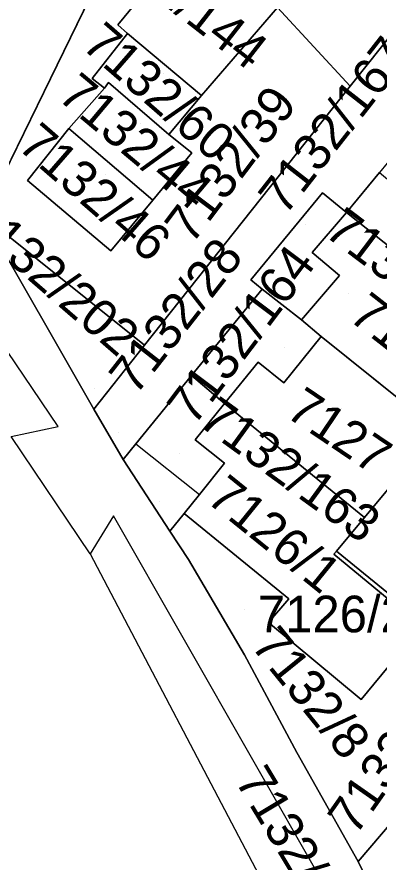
# Model space of a CAD drawing. Extents: x -266199 to -261993, y -1239047 to -1235108.
# Drawn here: x -263520.41 to -263500.66, y -1236178.02 to -1236131.86 of the extents above; entities that cross this region are included whole.
import ezdxf

# ---------------------------------------------------------------- set-up
doc = ezdxf.new("R2010")
doc.units = 0
for name, color, linetype in [('body_kn', 7, 'Continuous'), ('kladpar_druhypozemkov', 7, 'Continuous'), ('kladpar_hranice', 7, 'Continuous'), ('kladpar_parcelnecisla', 7, 'Continuous'), ('kladpar_plochy', 7, 'Continuous'), ('kladpar_sipky', 7, 'Continuous'), ('zappar_hrandruhpozemk', 7, 'Continuous')]:
    doc.layers.add(name, color=color, linetype=linetype)

msp = doc.modelspace()

# ---------------------------------------------------------------- linework, layer by layer
at = {"layer": 'body_kn'}
for p, q in [((-263514.91, -1236132.3), (-263514.91, -1236132.3)), ((-263514.38, -1236132.76), (-263514.38, -1236132.76)), ((-263516.31, -1236135.22), (-263516.31, -1236135.22)), ((-263515.41, -1236135.45), (-263515.41, -1236135.45)), ((-263515.64, -1236135.75), (-263515.64, -1236135.75)), ((-263502.23, -1236135.64), (-263502.23, -1236135.64)), ((-263510.35, -1236136.15), (-263510.35, -1236136.15)), ((-263510.35, -1236136.15), (-263510.35, -1236136.15)), ((-263517.58, -1236137.96), (-263517.58, -1236137.96)), ((-263517.58, -1236137.96), (-263517.58, -1236137.96)), ((-263512.12, -1236138.29), (-263512.12, -1236138.29)), ((-263510.87, -1236139.29), (-263510.87, -1236139.29)), ((-263519.84, -1236140.79), (-263519.84, -1236140.79)), ((-263503.75, -1236141.46), (-263503.75, -1236141.46)), ((-263503.75, -1236141.46), (-263503.75, -1236141.46)), ((-263512.99, -1236141.86), (-263512.99, -1236141.86)), ((-263512.99, -1236141.86), (-263512.99, -1236141.86)), ((-263502.44, -1236142.54), (-263502.44, -1236142.54)), ((-263502.44, -1236142.54), (-263502.44, -1236142.54)), ((-263515.29, -1236144.63), (-263515.29, -1236144.63)), ((-263504.3, -1236144.72), (-263504.3, -1236144.72)), ((-263502.81, -1236145.98), (-263502.81, -1236145.98)), ((-263507.65, -1236146.22), (-263507.65, -1236146.22)), ((-263507.03, -1236146.72), (-263507.03, -1236146.72)), ((-263504.88, -1236148.4), (-263504.88, -1236148.4)), ((-263504.88, -1236148.4), (-263504.88, -1236148.4)), ((-263503.81, -1236149.31), (-263503.81, -1236149.31)), ((-263503.81, -1236149.31), (-263503.81, -1236149.31)), ((-263513.45, -1236149.79), (-263513.45, -1236149.79)), ((-263507.26, -1236150.72), (-263507.26, -1236150.72)), ((-263510.89, -1236151.45), (-263510.89, -1236151.45)), ((-263510.89, -1236151.45), (-263510.89, -1236151.45)), ((-263505.86, -1236151.85), (-263505.86, -1236151.85)), ((-263509.09, -1236152.98), (-263509.09, -1236152.98)), ((-263516.21, -1236153.28), (-263516.21, -1236153.28)), ((-263516.21, -1236153.28), (-263516.21, -1236153.28)), ((-263518.16, -1236154.23), (-263518.16, -1236154.23)), ((-263518.16, -1236154.23), (-263518.16, -1236154.23)), ((-263510.69, -1236154.96), (-263510.69, -1236154.96)), ((-263513.93, -1236155.17), (-263513.93, -1236155.17)), ((-263513.93, -1236155.17), (-263513.93, -1236155.17)), ((-263514.62, -1236156.03), (-263514.62, -1236156.03)), ((-263514.62, -1236156.03), (-263514.62, -1236156.03)), ((-263509.09, -1236156.24), (-263509.09, -1236156.24)), ((-263510.45, -1236157.94), (-263510.45, -1236157.94)), ((-263510.45, -1236157.94), (-263510.45, -1236157.94)), ((-263515.14, -1236159.11), (-263515.14, -1236159.11)), ((-263511.29, -1236158.99), (-263511.29, -1236158.99)), ((-263511.29, -1236158.99), (-263511.29, -1236158.99)), ((-263501.45, -1236159.2), (-263501.45, -1236159.2)), ((-263512.07, -1236159.94), (-263512.07, -1236159.94)), ((-263512.07, -1236159.94), (-263512.07, -1236159.94)), ((-263516.41, -1236161.19), (-263516.41, -1236161.19)), ((-263516.41, -1236161.19), (-263516.41, -1236161.19)), ((-263503.12, -1236161.2), (-263503.12, -1236161.2)), ((-263503.12, -1236161.2), (-263503.12, -1236161.2)), ((-263502.98, -1236161.03), (-263502.98, -1236161.03)), ((-263511.06, -1236161.5), (-263511.06, -1236161.5)), ((-263505.57, -1236163.64), (-263505.57, -1236163.64)), ((-263506.69, -1236164.94), (-263506.69, -1236164.94)), ((-263508, -1236166.7), (-263508, -1236166.7)), ((-263501.64, -1236169.14), (-263501.64, -1236169.14)), ((-263505.14, -1236172.03), (-263505.14, -1236172.03)), ((-263501.79, -1236177.99), (-263501.79, -1236177.99))]:
    msp.add_line(p, q, dxfattribs=at)
at = {"layer": 'kladpar_druhypozemkov'}
for p, q in [((-263512.4, -1236134.97), (-263512.4, -1236134.97)), ((-263513.66, -1236137.67), (-263513.66, -1236137.67)), ((-263508.89, -1236138.85), (-263508.89, -1236138.85)), ((-263515.56, -1236140.44), (-263515.56, -1236140.44)), ((-263505.12, -1236145.98), (-263505.12, -1236145.98)), ((-263502.34, -1236146.95), (-263502.34, -1236146.95)), ((-263505.81, -1236149.91), (-263505.81, -1236149.91)), ((-263516.18, -1236152.13), (-263516.18, -1236152.13)), ((-263502.69, -1236153.25), (-263502.69, -1236153.25)), ((-263514.87, -1236154.53), (-263514.87, -1236154.53)), ((-263511.54, -1236155.68), (-263511.54, -1236155.68)), ((-263512.65, -1236158.34), (-263512.65, -1236158.34)), ((-263506.54, -1236158.92), (-263506.54, -1236158.92)), ((-263501.14, -1236162.66), (-263501.14, -1236162.66)), ((-263508, -1236164.25), (-263508, -1236164.25))]:
    msp.add_line(p, q, dxfattribs=at)
at = {"layer": 'kladpar_hranice'}
for p, q in [((-263503.75, -1236141.46), (-263502.44, -1236142.54)), ((-263502.44, -1236142.54), (-263495.11, -1236148.39)), ((-263503.81, -1236149.31), (-263499.04, -1236153.16)), ((-263509.09, -1236152.98), (-263510.89, -1236151.45))]:
    msp.add_line(p, q, dxfattribs=at)
for points in [[(-263510.25, -1236056.55), (-263509.34, -1236068.08), (-263508.78, -1236075.87), (-263508.53, -1236085.13), (-263507.31, -1236093.65), (-263507, -1236098.16), (-263506.93, -1236101.17), (-263507.02, -1236104.6), (-263507.26, -1236107.27), (-263507.94, -1236111.18), (-263508.5, -1236113.5), (-263509.38, -1236115.94), (-263510.54, -1236118.73), (-263522.26, -1236142.75)], [(-263501.54, -1236127.4), (-263502.26, -1236126.79), (-263507.09, -1236122.77), (-263510.96, -1236127.49), (-263514.91, -1236132.3), (-263514.38, -1236132.76), (-263516.31, -1236135.22), (-263515.64, -1236135.75), (-263517.58, -1236137.96), (-263519.84, -1236140.79), (-263515.29, -1236144.63), (-263512.99, -1236141.86), (-263510.87, -1236139.29), (-263512.12, -1236138.29), (-263510.35, -1236136.15), (-263506.2, -1236131.35), (-263502.23, -1236135.64), (-263513.45, -1236149.79), (-263522.26, -1236142.75), (-263510.54, -1236118.73), (-263500.84, -1236126.75), (-263501.54, -1236127.4)], [(-263498.03, -1236130.34), (-263502.23, -1236135.64), (-263506.2, -1236131.35), (-263502.26, -1236126.79), (-263501.54, -1236127.4), (-263498.03, -1236130.34)], [(-263506.2, -1236131.35), (-263510.35, -1236136.15), (-263514.38, -1236132.76), (-263514.91, -1236132.3), (-263510.96, -1236127.49), (-263506.2, -1236131.35)], [(-263514.62, -1236156.03), (-263516.21, -1236153.28), (-263513.45, -1236149.79), (-263502.23, -1236135.64), (-263498.03, -1236130.34), (-263497.41, -1236130.84), (-263499.87, -1236133.83), (-263497.35, -1236135.81), (-263498.77, -1236137.62), (-263498.54, -1236137.8), (-263500.64, -1236140.36), (-263502.44, -1236142.54), (-263503.75, -1236141.46), (-263507.65, -1236146.22), (-263507.03, -1236146.72), (-263510.89, -1236151.45), (-263513.93, -1236155.17), (-263514.62, -1236156.03)], [(-263510.35, -1236136.15), (-263512.12, -1236138.29), (-263515.41, -1236135.45), (-263515.64, -1236135.75), (-263516.31, -1236135.22), (-263514.38, -1236132.76), (-263510.35, -1236136.15)], [(-263517.58, -1236137.96), (-263515.64, -1236135.75), (-263515.41, -1236135.45), (-263512.12, -1236138.29), (-263510.87, -1236139.29), (-263512.99, -1236141.86), (-263517.58, -1236137.96)], [(-263512.99, -1236141.86), (-263515.29, -1236144.63), (-263519.84, -1236140.79), (-263517.58, -1236137.96), (-263512.99, -1236141.86)], [(-263492.76, -1236142.55), (-263491.31, -1236143.78), (-263495.11, -1236148.39), (-263502.44, -1236142.54), (-263500.64, -1236140.36)], [(-263504.88, -1236148.4), (-263507.03, -1236146.72), (-263507.65, -1236146.22), (-263503.75, -1236141.46)], [(-263522.26, -1236142.75), (-263516.21, -1236153.28), (-263514.62, -1236156.03), (-263512.07, -1236159.94), (-263511.06, -1236161.5), (-263508, -1236166.7), (-263505.14, -1236172.03), (-263501.79, -1236177.99), (-263500.21, -1236181.24), (-263498.9, -1236183.95), (-263497.65, -1236186.5), (-263496.56, -1236188.8), (-263492.22, -1236198.63), (-263490.17, -1236203.83), (-263488.26, -1236209.1), (-263484.59, -1236221.51), (-263481.5, -1236234.32), (-263480.57, -1236239.51), (-263477.77, -1236255.09), (-263476.89, -1236265.26)], [(-263516.21, -1236153.28), (-263522.26, -1236142.75), (-263513.45, -1236149.79), (-263516.21, -1236153.28)], [(-263504.88, -1236148.4), (-263502.81, -1236145.98), (-263504.3, -1236144.72), (-263502.44, -1236142.54)], [(-263502.44, -1236142.54), (-263504.3, -1236144.72), (-263502.81, -1236145.98), (-263504.88, -1236148.4)], [(-263510.89, -1236151.45), (-263507.03, -1236146.72), (-263504.88, -1236148.4), (-263503.81, -1236149.31)], [(-263495.11, -1236148.39), (-263499.04, -1236153.16), (-263503.81, -1236149.31), (-263504.88, -1236148.4)], [(-263509.09, -1236152.98), (-263507.26, -1236150.72), (-263505.86, -1236151.85), (-263503.81, -1236149.31)], [(-263503.81, -1236149.31), (-263505.86, -1236151.85), (-263507.26, -1236150.72), (-263509.09, -1236152.98)], [(-263512.07, -1236159.94), (-263514.62, -1236156.03), (-263513.93, -1236155.17), (-263510.89, -1236151.45), (-263509.09, -1236152.98)], [(-263510.45, -1236157.94), (-263509.09, -1236156.24), (-263510.69, -1236154.96), (-263509.09, -1236152.98)], [(-263509.09, -1236152.98), (-263510.69, -1236154.96), (-263509.09, -1236156.24), (-263510.45, -1236157.94)], [(-263509.09, -1236152.98), (-263501.45, -1236159.2), (-263502.98, -1236161.03), (-263503.12, -1236161.2)], [(-263499.04, -1236153.16), (-263497.49, -1236154.43), (-263501.45, -1236159.2), (-263509.09, -1236152.98)], [(-263494.63, -1236168.22), (-263498.34, -1236165.15), (-263498.18, -1236164.95), (-263502.98, -1236161.03), (-263501.45, -1236159.2), (-263497.49, -1236154.43), (-263489.56, -1236160.78), (-263489.65, -1236160.93), (-263493.09, -1236165.89), (-263494.47, -1236167.98), (-263494.63, -1236168.22)], [(-263510.45, -1236157.94), (-263511.29, -1236158.99), (-263512.07, -1236159.94)], [(-263503.12, -1236161.2), (-263498.34, -1236165.15), (-263501.64, -1236169.14), (-263506.69, -1236164.94), (-263505.57, -1236163.64), (-263511.29, -1236158.99), (-263510.45, -1236157.94)], [(-263511.29, -1236158.99), (-263505.57, -1236163.64), (-263506.69, -1236164.94), (-263501.64, -1236169.14), (-263498.34, -1236165.15), (-263494.63, -1236168.22), (-263496.43, -1236170.92), (-263499.88, -1236175.74), (-263501.79, -1236177.99), (-263505.14, -1236172.03), (-263508, -1236166.7), (-263511.06, -1236161.5), (-263512.07, -1236159.94), (-263511.29, -1236158.99)], [(-263498.34, -1236165.15), (-263503.12, -1236161.2), (-263502.98, -1236161.03), (-263498.18, -1236164.95), (-263498.34, -1236165.15)], [(-263500.21, -1236181.24), (-263501.79, -1236177.99), (-263499.88, -1236175.74), (-263497.84, -1236177.68), (-263500.21, -1236181.24)]]:
    msp.add_lwpolyline(points, dxfattribs=at)
at = {"layer": 'kladpar_plochy'}
msp.add_line((-263510.54, -1236118.73), (-263522.26, -1236142.75), dxfattribs=at)
for points in [[(-263501.54, -1236127.4), (-263502.26, -1236126.79), (-263507.09, -1236122.77), (-263510.96, -1236127.49), (-263514.91, -1236132.3), (-263514.38, -1236132.76), (-263516.31, -1236135.22), (-263515.64, -1236135.75), (-263517.58, -1236137.96), (-263519.84, -1236140.79), (-263515.29, -1236144.63), (-263512.99, -1236141.86), (-263510.87, -1236139.29), (-263512.12, -1236138.29), (-263510.35, -1236136.15), (-263506.2, -1236131.35), (-263502.23, -1236135.64), (-263513.45, -1236149.79), (-263522.26, -1236142.75), (-263510.54, -1236118.73), (-263500.84, -1236126.75)], [(-263498.03, -1236130.34), (-263502.23, -1236135.64), (-263506.2, -1236131.35), (-263502.26, -1236126.79), (-263501.54, -1236127.4)], [(-263506.2, -1236131.35), (-263510.35, -1236136.15), (-263514.38, -1236132.76), (-263514.91, -1236132.3), (-263510.96, -1236127.49)], [(-263514.62, -1236156.03), (-263516.21, -1236153.28), (-263513.45, -1236149.79), (-263502.23, -1236135.64), (-263498.03, -1236130.34), (-263497.41, -1236130.84), (-263499.87, -1236133.83), (-263497.35, -1236135.81), (-263498.77, -1236137.62), (-263498.54, -1236137.8), (-263500.64, -1236140.36), (-263502.44, -1236142.54), (-263503.75, -1236141.46), (-263507.65, -1236146.22), (-263507.03, -1236146.72), (-263510.89, -1236151.45), (-263513.93, -1236155.17)], [(-263510.35, -1236136.15), (-263512.12, -1236138.29), (-263515.41, -1236135.45), (-263515.64, -1236135.75), (-263516.31, -1236135.22), (-263514.38, -1236132.76)], [(-263517.58, -1236137.96), (-263515.64, -1236135.75), (-263515.41, -1236135.45), (-263512.12, -1236138.29), (-263510.87, -1236139.29), (-263512.99, -1236141.86)], [(-263512.99, -1236141.86), (-263515.29, -1236144.63), (-263519.84, -1236140.79), (-263517.58, -1236137.96)], [(-263492.76, -1236142.55), (-263491.31, -1236143.78), (-263495.11, -1236148.39), (-263502.44, -1236142.54), (-263500.64, -1236140.36), (-263499.1, -1236141.63), (-263497.07, -1236139.01)], [(-263503.75, -1236141.46), (-263502.44, -1236142.54), (-263504.3, -1236144.72), (-263502.81, -1236145.98), (-263504.88, -1236148.4), (-263507.03, -1236146.72), (-263507.65, -1236146.22)], [(-263516.21, -1236153.28), (-263522.26, -1236142.75), (-263513.45, -1236149.79)], [(-263495.11, -1236148.39), (-263499.04, -1236153.16), (-263503.81, -1236149.31), (-263504.88, -1236148.4), (-263502.81, -1236145.98), (-263504.3, -1236144.72), (-263502.44, -1236142.54)], [(-263510.89, -1236151.45), (-263507.03, -1236146.72), (-263504.88, -1236148.4), (-263503.81, -1236149.31), (-263505.86, -1236151.85), (-263507.26, -1236150.72), (-263509.09, -1236152.98)], [(-263499.04, -1236153.16), (-263497.49, -1236154.43), (-263501.45, -1236159.2), (-263509.09, -1236152.98), (-263507.26, -1236150.72), (-263505.86, -1236151.85), (-263503.81, -1236149.31)], [(-263512.07, -1236159.94), (-263514.62, -1236156.03), (-263513.93, -1236155.17), (-263510.89, -1236151.45), (-263509.09, -1236152.98), (-263510.69, -1236154.96), (-263509.09, -1236156.24), (-263510.45, -1236157.94), (-263511.29, -1236158.99)], [(-263503.12, -1236161.2), (-263498.34, -1236165.15), (-263501.64, -1236169.14), (-263506.69, -1236164.94), (-263505.57, -1236163.64), (-263511.29, -1236158.99), (-263510.45, -1236157.94), (-263509.09, -1236156.24), (-263510.69, -1236154.96), (-263509.09, -1236152.98), (-263501.45, -1236159.2), (-263502.98, -1236161.03)], [(-263494.63, -1236168.22), (-263498.34, -1236165.15), (-263498.18, -1236164.95), (-263502.98, -1236161.03), (-263501.45, -1236159.2), (-263497.49, -1236154.43), (-263489.56, -1236160.78), (-263489.65, -1236160.93), (-263493.09, -1236165.89), (-263494.47, -1236167.98)], [(-263511.29, -1236158.99), (-263505.57, -1236163.64), (-263506.69, -1236164.94), (-263501.64, -1236169.14), (-263498.34, -1236165.15), (-263494.63, -1236168.22), (-263496.43, -1236170.92), (-263499.88, -1236175.74), (-263501.79, -1236177.99), (-263505.14, -1236172.03), (-263508, -1236166.7), (-263511.06, -1236161.5), (-263512.07, -1236159.94)], [(-263498.34, -1236165.15), (-263503.12, -1236161.2), (-263502.98, -1236161.03), (-263498.18, -1236164.95)], [(-263500.21, -1236181.24), (-263501.79, -1236177.99), (-263499.88, -1236175.74), (-263497.84, -1236177.68)]]:
    msp.add_lwpolyline(points, close=True, dxfattribs=at)
msp.add_lwpolyline([(-263522.26, -1236142.75), (-263516.21, -1236153.28), (-263514.62, -1236156.03), (-263512.07, -1236159.94), (-263511.06, -1236161.5), (-263508, -1236166.7), (-263505.14, -1236172.03), (-263501.79, -1236177.99), (-263500.21, -1236181.24), (-263498.9, -1236183.95), (-263497.65, -1236186.5), (-263496.56, -1236188.8), (-263492.22, -1236198.63), (-263490.17, -1236203.83), (-263488.26, -1236209.1), (-263484.59, -1236221.51), (-263481.5, -1236234.32), (-263480.57, -1236239.51), (-263477.77, -1236255.09), (-263476.89, -1236265.26)], dxfattribs=at)
at = {"layer": 'kladpar_sipky'}
for p, q in [((-263504.68, -1236143.19), (-263504.68, -1236143.19)), ((-263510.86, -1236153.07), (-263510.86, -1236153.07)), ((-263501.59, -1236162.29), (-263501.59, -1236162.29))]:
    msp.add_line(p, q, dxfattribs=at)
at = {"layer": 'zappar_hrandruhpozemk'}
for p, q in [((-263513.93, -1236155.17), (-263510.45, -1236157.94)), ((-263515.14, -1236159.11), (-263516.41, -1236161.19)), ((-263503, -1236180.38), (-263515.14, -1236159.11)), ((-263516.41, -1236161.19), (-263505.25, -1236182.46))]:
    msp.add_line(p, q, dxfattribs=at)
for points in [[(-263518.16, -1236154.23), (-263523.75, -1236145.99), (-263523.93, -1236147.49), (-263524, -1236149.35)], [(-263516.41, -1236161.19), (-263520.73, -1236154.77), (-263518.16, -1236154.23)]]:
    msp.add_lwpolyline(points, dxfattribs=at)

# ---------------------------------------------------------------- texts
at = {"layer": 'kladpar_parcelnecisla'}
for s, rotation, p in [('7132/144', 322, (-263516.572, -1236127.97)), ('7132/60', 319, (-263516.95, -1236133.516)), ('7132/167', 52, (-263505.79, -1236142.775)), ('7132/44', 320, (-263518.264, -1236136.309)), ('7132/39', 53, (-263510.879, -1236144.351)), ('7132/46', 319, (-263520.446, -1236139.006)), ('7132/202', 319, (-263523.293, -1236143.18)), ('7132/165', 323, (-263503.724, -1236143.748)), ('7132/28', 52, (-263513.94, -1236152.593)), ('7132/164', 53, (-263510.749, -1236154.25)), ('7128', 322, (-263502.393, -1236148.357)), ('7127', 326, (-263505.831, -1236153.633)), ('7132/163', 324, (-263510.589, -1236154.113)), ('7126/1', 321, (-263510.153, -1236158.296)), ('7132/8', 309, (-263507.696, -1236166.21)), ('7132/173', 55, (-263501.936, -1236176.635)), ('7132/172', 301, (-263508.552, -1236173.564))]:
    msp.add_text(s, height=2, rotation=rotation, dxfattribs=at).set_placement(p)
msp.add_text('7126/2', height=2, dxfattribs=at).set_placement((-263507.267, -1236165.47))

doc.saveas('drawing.dxf')
